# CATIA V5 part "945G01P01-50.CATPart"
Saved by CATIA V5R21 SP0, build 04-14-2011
Part number: 945G01P01-50
Bounding box of the stored display mesh (mm): x -11.215 to 11.225, y -4.875 to 4.875, z -50.1 to -0.1
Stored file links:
  C:\Users\ALI OZGUN\Desktop\alhan\945G01P01-50.CATPart
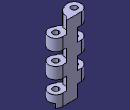
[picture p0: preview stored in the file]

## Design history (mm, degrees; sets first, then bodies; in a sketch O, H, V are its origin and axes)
Body1 (main body)
  Sketch1 on xy-plane, origin (0, 0, 0), H (1, 0, 0), V (0, 1, 0)
    construction line L1 (-6.35, 0) -> (6.35, 0)
    point P1 (-6.35, 0)
    point P2 (6.35, 0)
    line L2 (-6.35, 4.875) -> (6.35, 4.875)
    line L3 (6.35, -4.875) -> (-6.35, -4.875)
    arc A1 centre (6.35, 0) radius 4.875 from (6.35, 4.875) to (6.35, -4.875) cw
    arc A2 centre (-6.35, 0) radius 4.875 from (-6.35, -4.875) to (-6.35, 4.875) cw
    distance L1 L2 = 4.875
    length L1 = 12.7
    distance P2 V = 6.35
    coincidence: P1 H
    horizontal: L1 H
    tangency: A1 L2, A2 L2, A1 L3, A2 L3
  Pad1: profile Sketch1, direction (0, 0, 1), length 50.1, mirrored extent
  Body2
    Sketch2 on zx-plane, origin (0, 0, 0), H (-1, 0, 0), V (0, 0, 1)
      line L1 (-17.4249, -33.3) -> (-3.75, -33.3)
      line L2 (-3.75, -33.3) -> (-3.75, -42.1)
      line L3 (-3.75, -42.1) -> (-17.4249, -42.1)
      line L4 (-17.4249, -42.1) -> (-17.4249, -33.3)
      line L5 (3.75, -41.7) -> (15.9148, -41.7)
      line L6 (15.9148, -41.7) -> (15.9148, -50.5)
      line L7 (15.9148, -50.5) -> (3.75, -50.5)
      line L8 (3.75, -50.5) -> (3.75, -41.7)
      reference projected line E1 (-6.35, -50.1) -> (6.35, -50.1) from edge [start face of Pad1 | face of Pad1 from Sketch1.L2]
      reference projected line E2 (-6.35, -50.1) -> (6.35, -50.1) from edge [start face of Pad1 | face of Pad1 from Sketch1.L2]
      distance L3 E1 = 8
      length L4 = 8.8
      distance L2 L8 = 7.5
      distance L8 V = 3.75
      distance L5 L7 = 8.8
      distance L5 E2 = 8.4
      horizontal: L1 H, L3 H, L5 H, L7 H
      vertical: L2 V, L4 V, L6 V, L8 V
    Pad2: profile Sketch2, direction (0, 1, 0), length 20, mirrored extent
    RectPattern1: of the body so far, direction 1 instances 6, spacing 16.8, along axis of face of Pad1 from Sketch1.A2
  Remove1: tool Body2
  Sketch3 on xy-plane, origin (0, 0, 0), H (1, 0, 0), V (0, 1, 0)
    line L1 (-2.8809, -3.425) -> (2.8809, -3.425)
    reference projected line E1 (6.35, 4.875) -> (-6.35, 4.875) from edge [face of Pad1 from Sketch1.L2 | end face of Pad1]
    projected arc E2 centre (6.35, 0) radius 4.875 from (6.35, -4.875) to (6.35, 4.875) ccw from edge [face of Pad1 from Sketch1.A1 | face of RectPattern1]
    projected arc E3 centre (6.35, 0) radius 4.875 from (2.8809, -3.425) to (6.35, -4.875) ccw from edge [face of Pad1 from Sketch1.A1 | face of RectPattern1]
    projected arc E4 centre (-6.35, 0) radius 4.875 from (-6.35, 4.875) to (-6.35, -4.875) ccw from edge [face of Pad1 from Sketch1.A2 | end face of Pad1]
    projected arc E5 centre (-6.35, 0) radius 4.875 from (-6.35, -4.875) to (-2.8809, -3.425) ccw from edge [face of Pad1 from Sketch1.A2 | end face of Pad1]
    circle A1 centre (6.35, 0) radius 2
    point P7 (6.35, 0)
    circle A2 centre (-6.35, 0) radius 2
    point P8 (-6.35, 0)
    projected line E6 (-6.35, -4.875) -> (3.75, -4.875) from edge [face of Pad1 from Sketch1.L3 | end face of Pad1]
    projected line E7 (-6.35, -4.875) -> (6.35, -4.875) from edge [face of Pad1 from Sketch1.L3 | end face of Pad1]
    distance E1 L1 = 8.3
    radius A1 = 2
    radius A2 = 2
    horizontal: L1 H
    concentricity: P7 E2, P8 E4
  Pocket1: profile Sketch3, direction (0, 0, -1), length 50.1, mirrored extent
  Body3
    Solid1: linked copy from another document
    Translate1: Direction yz-plane, Length 25.4, ToTransfor Solid1
  Remove2: tool Body3
  Body4
    Solid2: solid without history
    Translate2: Direction yz-plane, Length -12.7, ToTransfor Solid2
    Thickness1: Face face of Solid2, Thickness 0.5
    Thickness2: Face (face of Solid2; face of Solid2; face of Solid2; face of Solid2; face of Solid2; face of Solid2; face of Solid2; face of Solid2; face of Solid2; face of Solid2; face of Solid2; face of Solid2), Thickness -2.5
    Thickness3: Face (face of Solid2; face of Solid2; face of Solid2; face of Solid2; face of Solid2; face of Solid2; face of Solid2; face of Solid2; face of Solid2; face of Solid2; face of Solid2; face of Solid2; face of Solid2; face of Solid2; face of Solid2; face of Solid2; face of Solid2; face of Solid2; face of Solid2; face of Solid2; face of Solid2; face of Solid2; face of Solid2; face of Solid2), Thickness 0.4
  Remove3: tool Body4
  Chamfer1: length 3, angle 45, on edge [face of Solid2 | face of Pocket1 from Sketch3.L1]; edge [face of Solid1 | face of Pocket1 from Sketch3.L1] (x6); edge [face of Pocket1 from Sketch3.L1 | face of Solid2] (x5)
  Sketch4 on start face of Pad1, origin (0, 0, -50.1), H (1, 0, 0), V (0, -1, 0)
    point P1 (6.35, -3.275)
    point P2 (-3.75, -3.275)
    arc A1 centre (6.35, 0) radius 3.25 from (3.1063, -0.2016) to (8.9441, -1.9578) ccw
    reference projected arc E1 centre (6.35, 0) radius 4.875 from (6.35, -4.875) to (6.35, 4.875) ccw from edge [start face of Pad1 | face of Pocket1]
    line L1 (3.1063, -0.2016) -> (2.8809, 3.425)
    reference projected point E2 (2.8809, 3.425) from edge [face of Pocket1 from Sketch3.L1 | face of Pocket1]
    projected arc E3 centre (6.35, 0) radius 4.875 from (6.35, -4.875) to (2.8809, 3.425) ccw from edge [start face of Pad1 | face of Pocket1]
    projected arc E4 centre (6.35, 0) radius 4.875 from (10.2924, -2.8676) to (2.8809, 3.425) ccw from edge [start face of Pad1 | face of Pocket1]
    line L2 (8.9441, -1.9578) -> (10.2924, -2.8676)
    distance P1 P2 = 10.1
    radius A1 = 3.25
    concentricity: A1 E1
    coincidence: L1 E2
    tangency: L1 A1
  Pocket2: profile Sketch4, direction (0, 0, 1), length 2.8
  Fillet1: radius 0.5, on edge [face of Pocket2 from Sketch4.L2 | face of Pocket2 from Sketch4.A1]; edge [face of Pocket1 | face of Pocket2 from Sketch4.L2]
  Sketch5 on face of Pad1 from Sketch1.L2, origin (0, 4.875, 0), H (-1, 0, 0), V (0, 0, 1)
    line L1 (37.9681, -0.1) -> (-29.1275, -0.1)
    line L2 (-29.1275, -0.1) -> (-29.1275, -62.0741)
    line L3 (-29.1275, -62.0741) -> (37.9681, -62.0741)
    line L4 (37.9681, -62.0741) -> (37.9681, -0.1)
    reference projected line E1 (3.75, -0.1) -> (6.35, -0.1) from edge [face of Pad1 from Sketch1.L2 | face of RectPattern1]
    horizontal: L1 H, L3 H
    vertical: L2 V, L4 V
    coincidence: L1 E1
  Pocket3: profile Sketch5, direction (0, -1, 0), length 16.8, opposite side length 12, outer side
